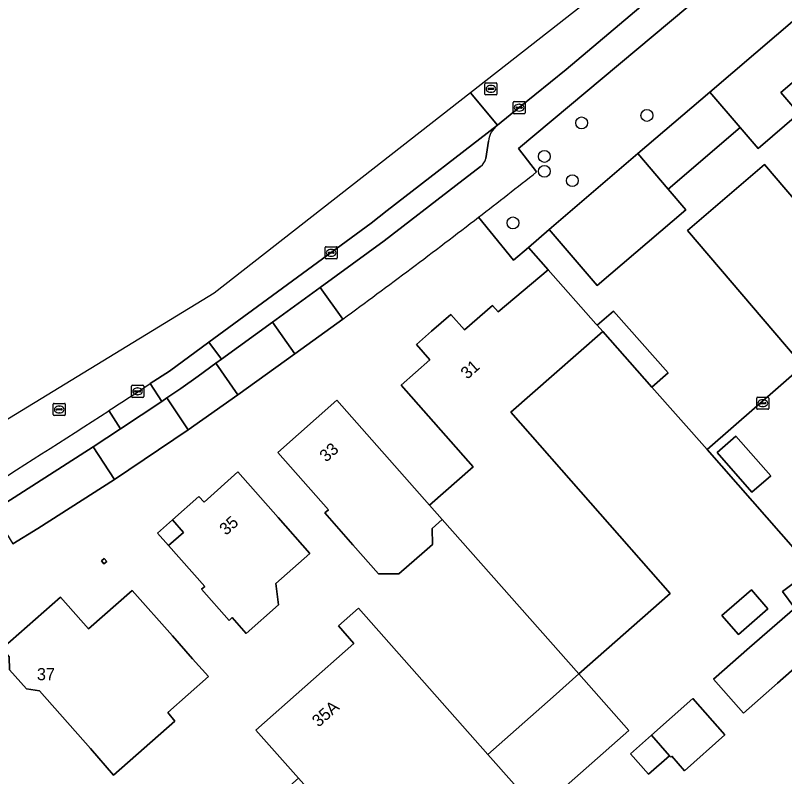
# Model space of a CAD drawing. Extents: x 157320 to 158835, y 386650 to 388491.
# Drawn here: x 157506.5 to 157569.8, y 387807.9 to 387870.6 of the extents above; entities that cross this region are included whole.
import ezdxf

# ---------------------------------------------------------------- set-up
doc = ezdxf.new("R2010")
doc.units = 0
for name, color, linetype in [('IMGEO_Boom', 7, 'Continuous'), ('IMGEO_Erf', 7, 'Continuous'), ('IMGEO_Groenvoorziening', 7, 'Continuous'), ('IMGEO_Kolk', 7, 'Continuous'), ('IMGEO_Pand', 7, 'Continuous'), ('IMGEO_Pand_nummerreeks', 7, 'Continuous'), ('IMGEO_Pand_overbouw', 7, 'Continuous'), ('IMGEO_Parkeervlak_open', 7, 'Continuous'), ('IMGEO_Rijbaan_lokaal_open', 7, 'Continuous'), ('IMGEO_Rioolput', 7, 'Continuous'), ('IMGEO_Voetpad_open', 7, 'Continuous')]:
    doc.layers.add(name, color=color, linetype=linetype)

msp = doc.modelspace()

# ---------------------------------------------------------------- linework, layer by layer
at = {"layer": 'IMGEO_Boom'}
for centre in [(157558.453, 387862.33), (157553.082, 387861.716), (157550.013, 387858.954), (157550.013, 387857.727), (157552.315, 387856.959), (157547.427, 387853.483)]:
    msp.add_circle(centre, 0.489, dxfattribs=at)
at = {"layer": 'IMGEO_Erf'}
for points in [[(157586.724, 387855.194), (157587.084, 387855.48), (157587.122, 387855.453), (157587.269, 387855.584), (157575.403, 387869.291), (157569.479, 387864.217), (157570.962, 387862.485), (157567.606, 387859.61), (157566.122, 387861.341), (157560.199, 387856.267), (157561.654, 387854.566), (157554.359, 387848.322), (157550.408, 387852.934), (157548.695, 387851.467), (157550.322, 387849.621), (157554.247, 387845.187), (157554.364, 387845.056), (157555.703, 387846.223), (157560.195, 387841.135), (157558.857, 387839.969), (157563.406, 387834.832), (157579.224, 387848.623)], [(157561.787, 387852.856), (157568.123, 387858.279), (157577.091, 387847.802), (157570.755, 387842.378)], [(157521.779, 387823.32), (157522.051, 387823.563), (157519.068, 387826.917), (157520.296, 387828.009), (157519.39, 387829.03), (157521.56, 387830.96), (157522, 387830.5), (157524.78, 387832.98), (157528.096, 387829.238), (157530.717, 387826.281), (157527.917, 387823.803), (157528.118, 387822.034), (157525.473, 387819.687), (157524.318, 387820.988), (157524.058, 387820.757)], [(157513.539, 387825.658), (157513.771, 387825.862), (157513.982, 387825.621), (157513.75, 387825.417)], [(157519.003, 387813.167), (157519.589, 387812.472), (157514.552, 387808.034), (157512.639, 387810.206), (157508.446, 387814.954), (157507.381, 387815.121), (157505.981, 387816.698), (157505.948, 387817.767), (157505.361, 387818.439), (157510.166, 387822.679), (157512.488, 387820.067), (157516.084, 387823.235), (157519.389, 387819.484), (157521.042, 387817.608), (157522.369, 387816.133)], [(157564.628, 387821.168), (157567.053, 387823.279), (157568.414, 387821.716), (157565.988, 387819.605)], [(157560.5, 387809.575), (157560.419, 387809.502), (157560.311, 387809.625), (157558.58, 387808.094), (157557.095, 387809.773), (157558.823, 387811.302), (157562.236, 387814.32), (157564.878, 387811.332), (157561.55, 387808.388)]]:
    msp.add_lwpolyline(points, close=True, dxfattribs=at)
for points in [[(157572.871, 387818.83), (157569.202, 387815.603), (157566.397, 387813.137), (157563.951, 387815.919), (157566.91, 387818.522), (157570.647, 387821.774), (157569.622, 387823.129), (157572.068, 387824.978), (157563.406, 387834.832), (157558.857, 387839.969), (157554.83, 387844.534), (157550.83, 387841.03), (157547.25, 387837.91), (157560.37, 387822.98), (157552.856, 387816.356), (157541.612, 387829.069), (157540.778, 387828.332), (157540.791, 387827.021), (157540.137, 387826.444), (157538.038, 387824.589), (157536.364, 387824.587), (157534.256, 387826.973), (157531.932, 387829.604), (157532.232, 387829.869), (157528.06, 387834.59), (157532.92, 387838.9), (157540.566, 387830.252), (157544.138, 387833.397), (157538.21, 387840.13), (157540.59, 387842.22), (157539.498, 387843.48), (157540.727, 387844.563), (157542.307, 387845.955), (157543.444, 387844.689), (157545.754, 387846.687), (157546.22, 387846.169), (157550.322, 387849.621), (157548.695, 387851.467), (157547.458, 387850.408), (157544.602, 387853.954)], [(157533.417, 387845.562), (157529.471, 387842.708), (157524.788, 387839.319), (157520.697, 387836.459), (157514.618, 387832.373), (157508.314, 387828.335), (157506.253, 387827.062)], [(157500.442, 387801.652), (157511.299, 387789.421), (157518.874, 387796.096), (157517.869, 387797.236), (157529.765, 387807.772), (157526.254, 387811.719), (157534.337, 387818.87), (157533.065, 387820.308), (157534.713, 387821.765), (157545.368, 387809.725), (157550.727, 387814.47), (157552.856, 387816.356), (157556.966, 387811.71), (157549.48, 387805.08), (157539.79, 387796.498), (157527.844, 387785.918), (157520.476, 387779.393), (157509.086, 387769.305), (157501.142, 387778.301), (157507.844, 387784.293), (157495.97, 387797.689)]]:
    msp.add_lwpolyline(points, dxfattribs=at)
msp.add_arc((157215.218, 388281.312), 539.563, 306.1381, 307.623, dxfattribs=at)
at = {"layer": 'IMGEO_Groenvoorziening'}
for points in [[(157563.624, 387864.255), (157572.906, 387872.206), (157568.709, 387877.067), (157547.894, 387859.6), (157549.378, 387857.677)], [(157544.602, 387853.954), (157547.458, 387850.408), (157548.695, 387851.467), (157550.408, 387852.934), (157557.704, 387859.184), (157563.624, 387864.255)]]:
    msp.add_lwpolyline(points, dxfattribs=at)
msp.add_arc((157203.334, 388296.67), 558.982, 307.62687, 308.24758, dxfattribs=at)
at = {"layer": 'IMGEO_Kolk'}
for p, q in [((157547.439, 387862.545), (157547.439, 387863.397)), ((157547.514, 387863.471), (157548.366, 387863.471)), ((157547.698, 387862.965), (157547.698, 387862.977)), ((157547.741, 387863.014), (157548.139, 387863.014)), ((157547.927, 387863.251), (157547.952, 387863.251)), ((157548.182, 387862.977), (157548.182, 387862.965)), ((157548.44, 387863.397), (157548.44, 387862.545)), ((157548.366, 387862.471), (157547.514, 387862.471)), ((157548.136, 387862.928), (157547.738, 387862.928)), ((157547.95, 387862.691), (157547.925, 387862.691)), ((157531.962, 387850.598), (157531.962, 387851.45)), ((157532.037, 387851.524), (157532.889, 387851.524)), ((157532.221, 387851.018), (157532.221, 387851.03)), ((157532.659, 387850.981), (157532.261, 387850.981)), ((157532.264, 387851.067), (157532.662, 387851.067)), ((157532.45, 387851.304), (157532.475, 387851.304)), ((157532.705, 387851.03), (157532.705, 387851.018)), ((157532.963, 387851.45), (157532.963, 387850.598)), ((157532.889, 387850.524), (157532.037, 387850.524)), ((157532.473, 387850.744), (157532.448, 387850.744)), ((157516.023, 387839.189), (157516.023, 387840.041)), ((157516.098, 387840.115), (157516.95, 387840.115)), ((157516.282, 387839.609), (157516.282, 387839.621)), ((157516.72, 387839.572), (157516.322, 387839.572)), ((157516.325, 387839.658), (157516.723, 387839.658)), ((157516.511, 387839.895), (157516.536, 387839.895)), ((157516.766, 387839.621), (157516.766, 387839.609)), ((157517.024, 387840.041), (157517.024, 387839.189)), ((157516.95, 387839.115), (157516.098, 387839.115)), ((157516.534, 387839.335), (157516.509, 387839.335)), ((157567.496, 387838.215), (157567.496, 387839.067)), ((157567.571, 387839.141), (157568.423, 387839.141)), ((157567.984, 387838.921), (157568.009, 387838.921)), ((157568.497, 387839.067), (157568.497, 387838.215)), ((157567.755, 387838.635), (157567.755, 387838.647)), ((157568.193, 387838.598), (157567.795, 387838.598)), ((157567.798, 387838.684), (157568.196, 387838.684)), ((157568.007, 387838.361), (157567.982, 387838.361)), ((157568.239, 387838.647), (157568.239, 387838.635)), ((157568.423, 387838.141), (157567.571, 387838.141))]:
    msp.add_line(p, q, dxfattribs=at)
for points in [[(157547.439, 387862.545), (157547.439, 387863.397)], [(157547.514, 387863.471), (157548.366, 387863.471)], [(157548.44, 387863.397), (157548.44, 387862.545)], [(157548.366, 387862.471), (157547.514, 387862.471)], [(157531.962, 387850.598), (157531.962, 387851.45)], [(157532.037, 387851.524), (157532.889, 387851.524)], [(157532.963, 387851.45), (157532.963, 387850.598)], [(157532.889, 387850.524), (157532.037, 387850.524)], [(157516.023, 387839.189), (157516.023, 387840.041)], [(157516.098, 387840.115), (157516.95, 387840.115)], [(157517.024, 387840.041), (157517.024, 387839.189)], [(157516.95, 387839.115), (157516.098, 387839.115)], [(157567.496, 387838.215), (157567.496, 387839.067)], [(157567.571, 387839.141), (157568.423, 387839.141)], [(157568.497, 387839.067), (157568.497, 387838.215)], [(157568.423, 387838.141), (157567.571, 387838.141)]]:
    msp.add_lwpolyline(points, dxfattribs=at)
for centre, radius, start, end in [((157547.516, 387863.395), 0.0765, 91.55205, 178.44795), ((157547.516, 387863.395), 0.0765, 91.55205, 178.44795), ((157547.738, 387862.974), 0.0403, 85.87752, 175.75265), ((157547.735, 387862.964), 0.0366, 178.93798, 274.71019), ((157548.139, 387862.971), 0.043, 264.86636, 352.45326), ((157548.143, 387862.976), 0.0386, 1.73085, 96.63898), ((157548.364, 387863.395), 0.0765, 1.55205, 88.44795), ((157548.364, 387863.395), 0.0765, 1.55205, 88.44795), ((157547.516, 387862.547), 0.0765, 181.55205, 268.44795), ((157547.516, 387862.547), 0.0765, 181.55205, 268.44795), ((157548.364, 387862.547), 0.0765, 271.55205, 358.44795), ((157548.364, 387862.547), 0.0765, 271.55205, 358.44795), ((157532.039, 387851.448), 0.0765, 91.55205, 178.44795), ((157532.039, 387851.448), 0.0765, 91.55205, 178.44795), ((157532.261, 387851.027), 0.0403, 85.87752, 175.75265), ((157532.258, 387851.017), 0.0366, 178.93798, 274.71019), ((157532.662, 387851.024), 0.043, 264.86636, 352.45326), ((157532.666, 387851.029), 0.0386, 1.73085, 96.63898), ((157532.887, 387851.448), 0.0765, 1.55205, 88.44795), ((157532.887, 387851.448), 0.0765, 1.55205, 88.44795), ((157532.039, 387850.6), 0.0765, 181.55205, 268.44795), ((157532.039, 387850.6), 0.0765, 181.55205, 268.44795), ((157532.887, 387850.6), 0.0765, 271.55205, 358.44795), ((157532.887, 387850.6), 0.0765, 271.55205, 358.44795), ((157516.1, 387840.039), 0.0765, 91.55205, 178.44795), ((157516.1, 387840.039), 0.0765, 91.55205, 178.44795), ((157516.322, 387839.618), 0.0403, 85.87752, 175.75265), ((157516.319, 387839.608), 0.0366, 178.93798, 274.71019), ((157516.723, 387839.615), 0.043, 264.86636, 352.45326), ((157516.727, 387839.62), 0.0386, 1.73085, 96.63898), ((157516.948, 387840.039), 0.0765, 1.55205, 88.44795), ((157516.948, 387840.039), 0.0765, 1.55205, 88.44795), ((157516.1, 387839.191), 0.0765, 181.55205, 268.44795), ((157516.1, 387839.191), 0.0765, 181.55205, 268.44795), ((157516.948, 387839.191), 0.0765, 271.55205, 358.44795), ((157516.948, 387839.191), 0.0765, 271.55205, 358.44795), ((157567.573, 387839.065), 0.0765, 91.55205, 178.44795), ((157567.573, 387839.065), 0.0765, 91.55205, 178.44795), ((157568.421, 387839.065), 0.0765, 1.55205, 88.44795), ((157568.421, 387839.065), 0.0765, 1.55205, 88.44795), ((157567.795, 387838.644), 0.0403, 85.87752, 175.75265), ((157567.792, 387838.634), 0.0366, 178.93798, 274.71019), ((157568.196, 387838.641), 0.043, 264.86636, 352.45326), ((157568.2, 387838.646), 0.0386, 1.73085, 96.63898), ((157567.573, 387838.217), 0.0765, 181.55205, 268.44795), ((157567.573, 387838.217), 0.0765, 181.55205, 268.44795), ((157568.421, 387838.217), 0.0765, 271.55205, 358.44795), ((157568.421, 387838.217), 0.0765, 271.55205, 358.44795)]:
    msp.add_arc(centre, radius, start, end, dxfattribs=at)
for centre, major_axis, ratio, start_param, end_param in [((157547.926, 387862.971), (-0.387, 0.002), 0.722429, 4.712389, 7.853982), ((157547.951, 387862.971), (-0.39, 0.002), 0.717154, 1.570796, 4.712389), ((157532.449, 387851.024), (-0.387, 0.002), 0.722429, 4.712389, 7.853982), ((157532.474, 387851.024), (-0.39, 0.002), 0.717154, 1.570796, 4.712389), ((157516.51, 387839.615), (-0.387, 0.002), 0.722429, 4.712389, 7.853982), ((157516.535, 387839.615), (-0.39, 0.002), 0.717154, 1.570796, 4.712389), ((157567.983, 387838.641), (-0.387, 0.002), 0.722429, 4.712389, 7.853982), ((157568.008, 387838.641), (-0.39, 0.002), 0.717154, 1.570796, 4.712389)]:
    msp.add_ellipse(centre, major_axis=major_axis, ratio=ratio, start_param=start_param, end_param=end_param, dxfattribs=at)
at = {"layer": 'IMGEO_Pand'}
for points in [[(157575.403, 387869.291), (157572.906, 387872.206), (157563.624, 387864.255), (157566.122, 387861.341), (157567.606, 387859.61), (157570.962, 387862.485), (157569.479, 387864.217)], [(157566.122, 387861.341), (157563.624, 387864.255), (157557.704, 387859.184), (157560.199, 387856.267)], [(157561.654, 387854.566), (157560.199, 387856.267), (157557.704, 387859.184), (157550.408, 387852.934), (157554.359, 387848.322)], [(157568.123, 387858.279), (157561.787, 387852.856), (157570.755, 387842.378), (157577.091, 387847.802)], [(157547.25, 387837.91), (157550.83, 387841.03), (157554.83, 387844.534), (157554.364, 387845.056), (157554.247, 387845.187), (157550.322, 387849.621), (157546.22, 387846.169), (157545.754, 387846.687), (157543.444, 387844.689), (157542.307, 387845.955), (157540.727, 387844.563), (157539.498, 387843.48), (157540.59, 387842.22), (157538.21, 387840.13), (157544.138, 387833.397), (157540.566, 387830.252), (157541.612, 387829.069), (157552.856, 387816.356), (157560.37, 387822.98)], [(157555.703, 387846.223), (157554.364, 387845.056), (157554.83, 387844.534), (157558.857, 387839.969), (157560.195, 387841.135)], [(157532.92, 387838.9), (157528.06, 387834.59), (157532.232, 387829.869), (157531.932, 387829.604), (157534.256, 387826.973), (157536.364, 387824.587), (157538.038, 387824.589), (157540.137, 387826.444), (157540.791, 387827.021), (157540.778, 387828.332), (157541.612, 387829.069), (157540.566, 387830.252)], [(157567.107, 387831.306), (157568.65, 387832.651), (157565.787, 387835.935), (157564.244, 387834.59)], [(157528.096, 387829.238), (157524.78, 387832.98), (157522, 387830.5), (157521.56, 387830.96), (157519.39, 387829.03), (157520.296, 387828.009), (157519.068, 387826.917), (157522.051, 387823.563), (157521.779, 387823.32), (157524.058, 387820.757), (157524.318, 387820.988), (157525.473, 387819.687), (157528.118, 387822.034), (157527.917, 387823.803), (157530.717, 387826.281)], [(157513.771, 387825.862), (157513.539, 387825.658), (157513.75, 387825.417), (157513.982, 387825.621)], [(157522.369, 387816.133), (157521.042, 387817.608), (157519.389, 387819.484), (157516.084, 387823.235), (157512.488, 387820.067), (157510.166, 387822.679), (157505.361, 387818.439), (157505.948, 387817.767), (157505.981, 387816.698), (157507.381, 387815.121), (157508.446, 387814.954), (157512.639, 387810.206), (157514.552, 387808.034), (157519.589, 387812.472), (157519.003, 387813.167)], [(157564.628, 387821.168), (157565.988, 387819.605), (157568.414, 387821.716), (157567.053, 387823.279)], [(157539.79, 387796.498), (157549.48, 387805.08), (157545.368, 387809.725), (157534.713, 387821.765), (157533.065, 387820.308), (157534.337, 387818.87), (157526.254, 387811.719), (157529.765, 387807.772)], [(157572.871, 387818.83), (157570.647, 387821.774), (157566.91, 387818.522), (157563.951, 387815.919), (157566.397, 387813.137), (157569.202, 387815.603)], [(157556.966, 387811.71), (157552.856, 387816.356), (157550.727, 387814.47), (157545.368, 387809.725), (157549.48, 387805.08)], [(157564.878, 387811.332), (157562.236, 387814.32), (157558.823, 387811.302), (157560.311, 387809.625), (157560.419, 387809.502), (157560.5, 387809.575), (157561.55, 387808.388)], [(157560.311, 387809.625), (157558.823, 387811.302), (157557.095, 387809.773), (157558.58, 387808.094)]]:
    msp.add_lwpolyline(points, close=True, dxfattribs=at)
at = {"layer": 'IMGEO_Pand_overbouw'}
msp.add_lwpolyline([(157519.39, 387829.03), (157518.161, 387827.937), (157519.068, 387826.917), (157520.296, 387828.009)], close=True, dxfattribs=at)
at = {"layer": 'IMGEO_Parkeervlak_open'}
for points in [[(157546.147, 387861.518), (157537.066, 387854.492), (157535.745, 387853.47), (157522.393, 387843.675), (157523.426, 387842.267), (157527.643, 387845.306), (157531.562, 387848.157), (157536.811, 387852.004)], [(157545.185, 387858.784), (157545.401, 387860.213)], [(157536.811, 387852.004), (157542.733, 387856.568), (157544.765, 387858.134)], [(157518.506, 387838.793), (157517.57, 387840.255)], [(157514.156, 387838.026), (157515.108, 387836.538), (157518.506, 387838.793)]]:
    msp.add_lwpolyline(points, dxfattribs=at)
for centre, radius, start, end in [((157547.371, 387859.952), 1.987, 128.02429, 172.46704), ((157544.18, 387858.973), 1.023, 304.90543, 349.35722), ((157085.557, 388498.209), 787.107, 302.992116, 303.28891)]:
    msp.add_arc(centre, radius, start, end, dxfattribs=at)
at = {"layer": 'IMGEO_Rijbaan_lokaal_open'}
for points in [[(157663.311, 387953.76), (157658.238, 387959.617), (157554.626, 387872.571), (157543.925, 387864.194)], [(157543.925, 387864.194), (157546.147, 387861.518), (157547.942, 387862.974), (157551.801, 387866.114), (157557.951, 387871.301), (157565.965, 387878.024), (157573.629, 387884.467), (157593.222, 387900.95), (157607.65, 387912.915), (157608.065, 387913.264), (157650.183, 387948.684), (157650.72, 387949.134), (157653.615, 387951.569), (157655.198, 387952.9)], [(157517.57, 387840.255), (157519.144, 387841.291), (157522.393, 387843.675), (157535.745, 387853.47), (157537.066, 387854.492), (157546.147, 387861.518), (157543.925, 387864.194), (157522.839, 387847.686), (157443.622, 387799.36), (157428.091, 387777.362), (157415.846, 387729.438), (157404.023, 387683.166), (157393.08, 387676.277)], [(157587.573, 387855.855), (157587.269, 387855.584), (157587.122, 387855.453), (157587.084, 387855.48), (157586.724, 387855.194), (157579.224, 387848.623), (157563.406, 387834.832), (157572.068, 387824.978), (157569.622, 387823.129), (157570.647, 387821.774), (157572.871, 387818.83), (157578.014, 387812.108), (157580.938, 387808.286), (157581.633, 387808.779), (157591.473, 387797.447), (157594.723, 387800.331), (157589.404, 387806.433), (157588.409, 387807.574), (157588.317, 387807.49), (157585.327, 387810.951), (157578.552, 387818.795)]]:
    msp.add_lwpolyline(points, dxfattribs=at)
msp.add_lwpolyline([(157567.107, 387831.306), (157564.244, 387834.59), (157565.787, 387835.935), (157568.65, 387832.651)], close=True, dxfattribs=at)
for centre, radius, start, end in [((157085.557, 388498.209), 787.107, 302.992116, 303.28891), ((157072.803, 388517.613), 810.328, 302.071267, 303.001399)]:
    msp.add_arc(centre, radius, start, end, dxfattribs=at)
at = {"layer": 'IMGEO_Rioolput'}
for p, q in [((157545.111, 387864.09), (157545.111, 387864.942)), ((157545.186, 387865.016), (157546.038, 387865.016)), ((157546.112, 387864.942), (157546.112, 387864.09)), ((157545.37, 387864.51), (157545.37, 387864.522)), ((157545.808, 387864.473), (157545.41, 387864.473)), ((157545.413, 387864.559), (157545.811, 387864.559)), ((157545.622, 387864.236), (157545.597, 387864.236)), ((157545.599, 387864.796), (157545.624, 387864.796)), ((157545.854, 387864.522), (157545.854, 387864.51)), ((157546.038, 387864.016), (157545.186, 387864.016)), ((157509.571, 387837.702), (157509.571, 387838.554)), ((157509.646, 387838.628), (157510.498, 387838.628)), ((157510.059, 387838.408), (157510.084, 387838.408)), ((157510.572, 387838.554), (157510.572, 387837.702)), ((157510.498, 387837.628), (157509.646, 387837.628)), ((157509.83, 387838.122), (157509.83, 387838.134)), ((157510.268, 387838.085), (157509.87, 387838.085)), ((157509.873, 387838.171), (157510.271, 387838.171)), ((157510.082, 387837.848), (157510.057, 387837.848)), ((157510.314, 387838.134), (157510.314, 387838.122))]:
    msp.add_line(p, q, dxfattribs=at)
for points in [[(157545.111, 387864.09), (157545.111, 387864.942)], [(157545.186, 387865.016), (157546.038, 387865.016)], [(157546.112, 387864.942), (157546.112, 387864.09)], [(157546.038, 387864.016), (157545.186, 387864.016)], [(157509.571, 387837.702), (157509.571, 387838.554)], [(157509.646, 387838.628), (157510.498, 387838.628)], [(157510.572, 387838.554), (157510.572, 387837.702)], [(157510.498, 387837.628), (157509.646, 387837.628)]]:
    msp.add_lwpolyline(points, dxfattribs=at)
for centre, radius, start, end in [((157545.188, 387864.94), 0.0765, 91.55205, 178.44795), ((157545.188, 387864.94), 0.0765, 91.55205, 178.44795), ((157546.036, 387864.94), 0.0765, 1.55205, 88.44795), ((157546.036, 387864.94), 0.0765, 1.55205, 88.44795), ((157545.41, 387864.519), 0.0403, 85.87752, 175.75265), ((157545.407, 387864.509), 0.0366, 178.93798, 274.71019), ((157545.811, 387864.516), 0.043, 264.86636, 352.45326), ((157545.815, 387864.521), 0.0386, 1.73085, 96.63898), ((157545.188, 387864.092), 0.0765, 181.55205, 268.44795), ((157545.188, 387864.092), 0.0765, 181.55205, 268.44795), ((157546.036, 387864.092), 0.0765, 271.55205, 358.44795), ((157546.036, 387864.092), 0.0765, 271.55205, 358.44795), ((157509.648, 387838.552), 0.0765, 91.55205, 178.44795), ((157509.648, 387838.552), 0.0765, 91.55205, 178.44795), ((157510.496, 387838.552), 0.0765, 1.55205, 88.44795), ((157510.496, 387838.552), 0.0765, 1.55205, 88.44795), ((157509.648, 387837.704), 0.0765, 181.55205, 268.44795), ((157509.648, 387837.704), 0.0765, 181.55205, 268.44795), ((157509.87, 387838.131), 0.0403, 85.87752, 175.75265), ((157509.867, 387838.121), 0.0366, 178.93798, 274.71019), ((157510.271, 387838.128), 0.043, 264.86636, 352.45326), ((157510.275, 387838.133), 0.0386, 1.73085, 96.63898), ((157510.496, 387837.704), 0.0765, 271.55205, 358.44795), ((157510.496, 387837.704), 0.0765, 271.55205, 358.44795)]:
    msp.add_arc(centre, radius, start, end, dxfattribs=at)
for centre, major_axis, ratio, start_param, end_param in [((157545.598, 387864.516), (-0.387, 0.002), 0.722429, 4.712389, 7.853982), ((157545.623, 387864.516), (-0.39, 0.002), 0.717154, 1.570796, 4.712389), ((157510.058, 387838.128), (-0.387, 0.002), 0.722429, 4.712389, 7.853982), ((157510.083, 387838.128), (-0.39, 0.002), 0.717154, 1.570796, 4.712389)]:
    msp.add_ellipse(centre, major_axis=major_axis, ratio=ratio, start_param=start_param, end_param=end_param, dxfattribs=at)
at = {"layer": 'IMGEO_Voetpad_open'}
for points in [[(157593.222, 387900.95), (157573.629, 387884.467), (157574.301, 387883.673), (157566.639, 387877.223), (157565.965, 387878.024), (157557.951, 387871.301), (157551.801, 387866.114), (157547.942, 387862.974), (157546.147, 387861.518)], [(157549.378, 387857.677), (157547.894, 387859.6), (157568.709, 387877.067)], [(157545.401, 387860.213), (157545.185, 387858.784)], [(157544.765, 387858.134), (157542.733, 387856.568), (157536.811, 387852.004), (157531.562, 387848.157), (157533.417, 387845.562)], [(157512.873, 387835.055), (157515.108, 387836.538), (157514.156, 387838.026)], [(157503.066, 387830.951), (157504.041, 387829.429), (157504.568, 387829.753), (157512.873, 387835.055)]]:
    msp.add_lwpolyline(points, dxfattribs=at)
for points in [[(157529.471, 387842.708), (157533.417, 387845.562), (157531.562, 387848.157), (157527.643, 387845.306)], [(157529.471, 387842.708), (157527.643, 387845.306), (157523.426, 387842.267), (157522.972, 387841.94), (157524.788, 387839.319)], [(157522.972, 387841.94), (157523.426, 387842.267), (157522.393, 387843.675), (157519.144, 387841.291), (157517.57, 387840.255), (157518.506, 387838.793), (157518.927, 387839.073), (157520.077, 387839.855), (157521.504, 387840.878)], [(157520.697, 387836.459), (157524.788, 387839.319), (157522.972, 387841.94), (157521.504, 387840.878), (157520.077, 387839.855), (157518.927, 387839.073)], [(157520.697, 387836.459), (157518.927, 387839.073), (157518.506, 387838.793), (157515.108, 387836.538), (157512.873, 387835.055), (157514.618, 387832.373)], [(157512.873, 387835.055), (157504.568, 387829.753), (157506.253, 387827.062), (157508.314, 387828.335), (157514.618, 387832.373)]]:
    msp.add_lwpolyline(points, close=True, dxfattribs=at)
for centre, radius, start, end in [((157547.371, 387859.952), 1.987, 128.02429, 172.46704), ((157544.18, 387858.973), 1.023, 304.90543, 349.35722), ((157203.334, 388296.67), 558.982, 307.62687, 308.24758), ((157215.218, 388281.312), 539.563, 306.1381, 307.623), ((157072.803, 388517.613), 810.328, 302.071267, 303.001399)]:
    msp.add_arc(centre, radius, start, end, dxfattribs=at)

# ---------------------------------------------------------------- texts
at = {"layer": 'IMGEO_Pand_nummerreeks'}
for s, rotation, p in [('31', 41.51079, (157543.665, 387840.56)), ('33', 41.56809, (157532.048, 387833.742)), ('35', 41.73425, (157523.803, 387827.712)), ('35A', 41.56814, (157531.427, 387811.926))]:
    msp.add_text(s, height=1, rotation=rotation, dxfattribs=at).set_placement(p)
msp.add_text('37', height=1, dxfattribs=at).set_placement((157508.234, 387815.837))

doc.saveas('drawing.dxf')
